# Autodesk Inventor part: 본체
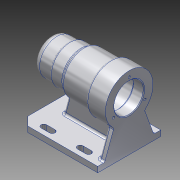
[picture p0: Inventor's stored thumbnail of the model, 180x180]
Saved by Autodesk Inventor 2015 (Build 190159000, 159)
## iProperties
Created: 2017-09
Part Number: 본체
Material: 알루미늄 6061
Document SubType Name: Modeling
Designer: owner
Density: 2.7 g/cm^3
Appearance: 알루미늄 - 평지
Mass: 692.85 g
Surface Area: 710.882 cm^2
Volume: 256.611 cm^3
Author: owner
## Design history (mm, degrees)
sketch "스케치1"
  geometry: L1 (-56, 0)-(56, 0); L2 (-56, 0)-(-56, 25); L3 (-56, 25)-(-31, 25); L4 (-31, 25)-(-31, 27); L5 (-31, 27)-(-11, 27); L6 (-11, 27)-(-11, 30); L7 (-11, 30)-(28, 30); L8 (28, 30)-(28, 34); L9 (28, 34)-(56, 34); L10 (56, 34)-(56, 0); 2 further points
  constraints: 20 end point, 8 perpendicular, 1 coincident, 1 horizontal, 1 midpoint, 1 vertical
  dimensions: "d0" = 112 distance of L1.start L1.end; "d1" = 50 diameter of L3 L1; "d2" = 54 diameter of L5 L1; "d3" = 60 diameter of L7 L1; "d4" = 68 diameter of L9 L1; "d5" = 25 distance of L2.end L3.end; "d6" = 45 distance between parallel lines of L6 L2; "d7" = 84 distance between parallel lines of L8 L2
revolve "회전1" sketch "스케치1" stored, may be unused: angle "d8" = 90 deg
fillet "모깎기1" dims "d9" = 9
sketch "스케치2"
  geometry: L1 (-56, -16)-(-56, 16) reference; L2 (56, -34)-(56, 34) reference; L3 (-56, 0)-(56, 0); L4 (-50, 0)-(-50, 10.5); L5 (-50, 10.5)-(-47, 10.5); L6 (-47, 10.5)-(-47, 16); L7 (-47, 16)-(-43, 16); L8 (-43, 16)-(-43, 17.5); L9 (-43, 17.5)-(-25, 17.5); L10 (-25, 17.5)-(-25, 21); L11 (-25, 21)-(-13, 21); L12 (-13, 21)-(-13, 24); L13 (-13, 24)-(41, 24); L14 (41, 24)-(41, 21); L15 (41, 21)-(56, 21); L16 (56, 21)-(56, 0); 1 further point
  constraints: 28 end point, 10 perpendicular, 4 point on line, 2 midpoint, 1 horizontal, 1 vertical
  dimensions: "d10" = 21 diameter of L5 L3; "d11" = 32 diameter of L7 L3; "d12" = 35 diameter of L9 L3; "d13" = 42 diameter of L11 L3; "d14" = 48 diameter of L13 L3; "d15" = 3 distance of L4.end L5.end; "d16" = 4 distance of L6.end L7.end; "d17" = 18 distance of L8.end L9.end; "d18" = 12 distance of L10.end L11.end; "d19" = 54 distance of L12.end L13.end; "d20" = 15 distance of L14.end L15.end
revolve "회전2" sketch "스케치2" stored, may be unused: angle "d21" = 90 deg
fillet "모깎기2" dims "d22" = 3
fillet "모깎기3" dims "d23" = 0.3
chamfer "모따기1" distance "d24" = 1; stored, may be unused: second distance "d25" = 2, angle "d26" = 45 deg
sketch "스케치3" dims "d27" = 52
  geometry: C1 r 22 at (0, 0) reference; 2 further points
  constraints: 1 coincident, 1 vertical alignment, 2 other
hole "구멍1" sketch "스케치3" at (0, 26) diameter "d28" = 3.242; stored, may be unused: countersink angle "d32" = 90 deg, drill point angle "d34" = 118 deg; dims "d29" = 8, "d30" = 4, "d31" = 2, "d33" = 11
node "작업 평면1"
sketch "스케치4"
  geometry: L1 (56, 45)-(-56, 45); L2 (-56, 45)-(-56, -45); L3 (-56, -45)-(56, -45); L4 (56, -45)-(56, 45); L5 (56, 45)-(-56, -45); L6 (-56, 45)-(56, -45); 1 further point
  constraints: 12 end point, 2 midpoint, 2 parallel, 1 horizontal, 1 perpendicular
  dimensions: "d39" = 112 distance of L3.end L2.end; "d40" = 90 distance of L2.end L1.end
extrude "돌출1" join sketch "스케치4" distance "d41" = 8; taper "d42" = 0 deg
sketch "스케치6"
  geometry: L1 (0, 8)-(90, 8) reference; L2 (0, 0)-(0, 8) reference; L3 (23.1, 43.992)-(10, 8); L4 (10, 8)-(80, 8); L5 (80, 8)-(66.9, 43.992); A1 r 34 centre (45, 70) between (23.1, 43.992) and (66.9, 43.992) reference; A2 r 34 centre (45, 70) between (23.1, 43.992) and (66.9, 43.992); 2 further points
  constraints: 6 end point, 4 point on circle, 2 point on line, 1 centre point, 1 coincident, 1 midpoint, 1 vertical alignment
  dimensions: "d51" = 10 distance from line of L2 L3.end; "d52" = 110 deg angle of L1 L5; "d53" = 110 deg angle of L1 L3
extrude "돌출3" join sketch "스케치6" distance "d54" = 8; taper "d55" = 0 deg
sketch "스케치7"
  geometry: L1 (-56, 45)-(-56, -45) reference; L2 (56, -4)-(-34, -4); L3 (-34, -4)-(-34, 4); L4 (-34, 4)-(56, 4); L5 (56, 4)-(56, -4); L6 (56, -45)-(56, 45) reference; 2 further points
  constraints: 8 end point, 2 parallel, 1 collinear, 1 horizontal, 1 horizontal alignment, 1 midpoint, 1 perpendicular
  dimensions: "d56" = 22 distance between parallel lines of L3 L1; "d57" = 8 distance of L2.end L3.end
extrude "돌출4" join sketch "스케치7" stored distance "d58" = 8; taper "d59" = 0 deg
feature "면 기울기2" dims angle "d60" = 15 deg
sketch "스케치8"
  geometry: L1 (-32, 34)-(-20, 34); L2 (-32, 30)-(-20, 30); L3 (-20, 38)-(-32, 38); L4 (20, 34)-(32, 34); L5 (20, 38)-(32, 38); L6 (32, 30)-(20, 30); L7 (-32, -34)-(-20, -34); L8 (-32, -30)-(-20, -30); L9 (-20, -38)-(-32, -38); L10 (32, -34)-(20, -34); L11 (32, -30)-(20, -30); L12 (20, -38)-(32, -38); L13 (56, -45)-(56, 45) reference; A1 r 4 centre (-32, 34) between (-32, 38) and (-32, 30); A2 r 4 centre (-20, 34) between (-20, 30) and (-20, 38); A3 r 4 centre (20, 34) between (20, 38) and (20, 30); A4 r 4 centre (32, 34) between (32, 30) and (32, 38); A5 r 4 centre (-32, -34) between (-32, -30) and (-32, -38); A6 r 4 centre (-20, -34) between (-20, -38) and (-20, -30); A7 r 4 centre (32, -34) between (32, -38) and (32, -30); A8 r 4 centre (20, -34) between (20, -30) and (20, -38); 5 further points
  constraints: 32 end point, 16 point on circle, 16 tangent, 8 centre point, 5 parallel, 4 midpoint, 2 horizontal, 2 point on line
  dimensions: "d61" = 4 radius of A1; "d62" = 24 distance from line of L10.start L13; "d63" = 12 distance of L10.end L10.start; "d64" = 40 distance of L7.end L10.end; "d65" = 12 distance of L7.end L7.start; "d66" = 24 distance from line of L13 L4.end; "d67" = 12 distance of L4.start L4.end; "d68" = 40 distance of L1.end L4.start; "d69" = 12 distance of L1.start L1.end; "d70" = 34 vertical distance of point (-26, 34) point (0, 0); "d71" = 34 vertical distance of point (0, 0) point (26, 34); "d72" = 34 vertical distance of point (0, 0) point (-26, -34); "d73" = 4 radius of A3; "d74" = 4 radius of A5; "d75" = 4 radius of A8
extrude "돌출5" cut sketch "스케치8" stored distance "d76" = 0; taper "d77" = 0 deg
fillet "모깎기4" dims "d78" = 3
fillet "모깎기5" dims "d79" = 3
fillet "모깎기6" dims "d80" = 3
fillet "모깎기7" dims "d81" = 3
fillet "모깎기8" dims "d82" = 3
chamfer "모따기2" distance "d83" = 12; stored, may be unused: second distance "d84" = 12, angle "d85" = 45 deg
chamfer "모따기3" distance "d86" = 12; stored, may be unused: second distance "d87" = 12, angle "d88" = 45 deg
node "작업 평면2"
sketch "스케치9"
  geometry: L1 (-56, 34)-(-56, -24.711) reference; 2 further points
  constraints: 1 horizontal alignment, 1 other
  dimensions: "d90" = 48 distance from line of L1 point (-8, 0)
feature "엠보싱1" sketch "스케치9" dims "d0" = 112, "d1" = 50, "d2" = 54, "d3" = 60, "d4" = 68, "d5" = 25, "d6" = 45, "d7" = 84, "d91" = 0.5, "d92" = 0
node "솔리드1"
pattern_circular "원형 패턴1" dims angle "d36" = 360 deg
other parameters: "d89" = -69.75
